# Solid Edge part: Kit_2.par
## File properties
Sűrűség: 0,000 kg/m^3
Pontosság: 0,990
Author: bmolnar
Last saved by: bmolnar
Revision: 77
Username: bmolnar
Dokumentum tartalom típus: 0
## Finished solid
Body 1: solid body, 18 faces, 23 edges, 19 vertices, 2 separate solids.
  Faces by surface: plane 9, cylinder 6, cone 2, torus 1
  Edges by curve: circle 15, line 8
Bounding box of the edges (mm; curved faces can reach further): 22.800 x 22.200 x 4.900, from (-11.4, -11.4, 0.7) to (11.4, 10.8, 5.6).
Cylindrical faces by radius (mm): R8.8 x1, R10 x1, R10.05 x1, R10.8 x2, R11.4 x1
Conical faces (half-angle, radius in mm at the cone's reference point): 45 deg R8.55 x1, 45 deg R10.75 x1
Toroidal faces (ring radius, tube radius in mm): R9.2 r0.4 x1
Planar faces by outward normal: +z 3, -z 4, oblique 2
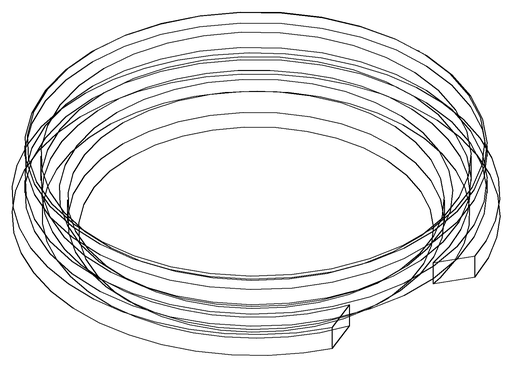
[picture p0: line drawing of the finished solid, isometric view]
